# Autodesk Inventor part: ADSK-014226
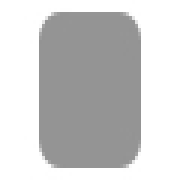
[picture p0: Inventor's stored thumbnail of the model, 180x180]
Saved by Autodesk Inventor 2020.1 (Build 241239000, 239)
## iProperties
Created: 2019-01
Part Number: ADSK-014226
Material: Stahl, weich
Document SubType Name: Modeling
Designer: lutzd
Language: de-DE
Size Designation: 5 x 39,384472 x 39,384472
Categories: <MemberInstance><Categories><Category DisplayName="Sonstige Bauteile" InternalName="5aa15e00-363f-49f2-933f-16f664388e3f" Mnemonic="OTHER"><Category DisplayName
Mass: 60.0398 g
Surface Area: 38.0412 cm^2
Volume: 7.64838 cm^3
Density: 7.85 g/cm^3
Appearance: Halbpoliert
IsCustomPart: 1
Title: Endcap
Author: lutzd
Revision Number: -
Dimensions: 39,4x39,4x5 mm
Mass: 0,06 kg
DocNumber: ADSK-014226
Folder: 01 - Themengebiete\Simplification\01 - Packaging machine\ADSK-014200\Frame\
VDS_Category: 3D Komponenten
VDS_NumSchm: Autodesk
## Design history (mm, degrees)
sketch "Sketch1"
  geometry: L1 (0, 20.175)-(0, -21.446); L2 (-20.203, 0)-(20.169, 0); L3 (-19.692, 19.692)-(19.692, 19.692); L4 (19.692, 19.692)-(19.692, -19.692); L5 (19.692, -19.692)-(-19.692, -19.692); L6 (-19.692, -19.692)-(-19.692, 19.692); 1 further point
  constraints: 12 end point, 2 horizontal, 2 parallel, 2 point on line, 1 perpendicular, 1 vertical
  dimensions: "d0" = 39.38447 distance between parallel lines of L5 L3 (= height); "d1" = 19.69224 distance between parallel lines of L2 L3 (= 0.5 x height); "d2" = 39.38447 distance between parallel lines of L6 L4 (= width); "d3" = 19.69224 distance between parallel lines of L6 L1 (= 0.5 x width)
extrude "Extrusion1" new body sketch "Sketch1" distance "d4" = 5 (= thickness); taper "d5" = 0 deg
fillet "Fillet1" dims "d6" = 5 (= fillet), "d7" = 0, "fillet" = 5 [user parameter; used in 1 equation term]
chamfer "Chamfer1" distance "d8" = 0 (computed from chamfer); stored, may be unused: second distance "d9" = 2, angle "d10" = 45 deg; dims "d11" = 0, "chamfer" = 0 [user parameter; used in 1 equation term]
body "Solid1"
other parameters: "thickness" = 5 [user parameter; used in 1 equation term], "width" = 39.38447 [user parameter; used in 2 equation terms], "height" = 39.38447 [user parameter; used in 2 equation terms]
